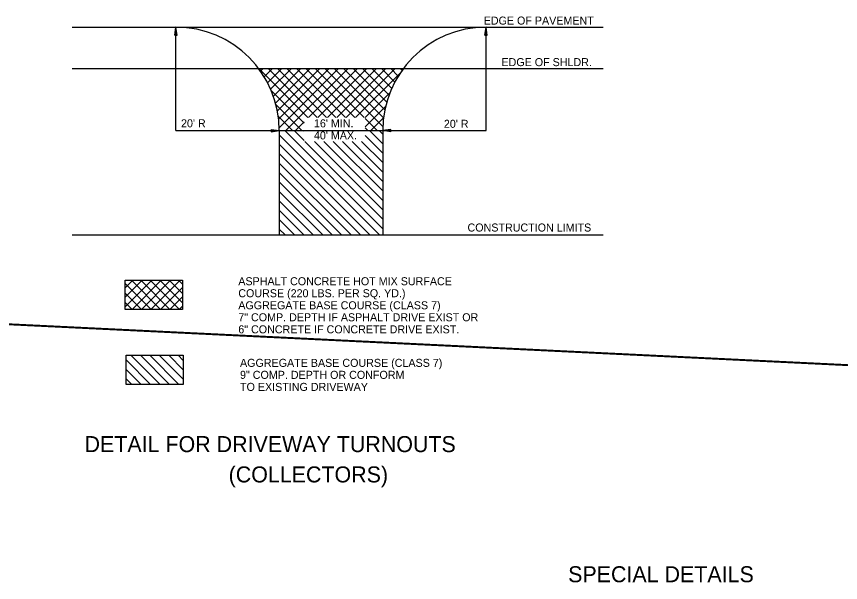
# Model space of a CAD drawing. Extents: x 1227242 to 1227801, y 152460 to 152569.
# Drawn here: x 1227362.27 to 1227375.13, y 152459.8 to 152468.63 of the extents above; entities that cross this region are included whole.
import ezdxf

# ---------------------------------------------------------------- set-up
doc = ezdxf.new("R2010")
doc.units = 0
for name, color, linetype in [('Default', 7, 'Continuous'), ('R_Dimension', 7, 'Continuous'), ('R_Draft', 7, 'Continuous')]:
    doc.layers.add(name, color=color, linetype=linetype)

msp = doc.modelspace()

# ---------------------------------------------------------------- linework, layer by layer
at = {"layer": 'Default'}
for p, q in [((1227364.737, 152468.337), (1227364.756, 152468.462)), ((1227364.737, 152468.337), (1227364.756, 152468.462)), ((1227364.74, 152468.337), (1227364.756, 152468.441)), ((1227364.74, 152468.337), (1227364.756, 152468.441)), ((1227364.756, 152466.847), (1227364.756, 152468.462)), ((1227364.774, 152468.337), (1227364.756, 152468.462)), ((1227364.774, 152468.337), (1227364.756, 152468.462)), ((1227364.771, 152468.337), (1227364.756, 152468.441)), ((1227364.771, 152468.337), (1227364.756, 152468.441)), ((1227369.58, 152468.337), (1227369.598, 152468.462)), ((1227369.58, 152468.337), (1227369.598, 152468.462)), ((1227369.583, 152468.337), (1227369.598, 152468.441)), ((1227369.583, 152468.337), (1227369.598, 152468.441)), ((1227369.598, 152466.847), (1227369.598, 152468.462)), ((1227369.617, 152468.337), (1227369.598, 152468.462)), ((1227369.617, 152468.337), (1227369.598, 152468.462)), ((1227369.614, 152468.337), (1227369.598, 152468.441)), ((1227369.614, 152468.337), (1227369.598, 152468.441)), ((1227364.737, 152468.337), (1227364.774, 152468.337)), ((1227364.737, 152468.337), (1227364.774, 152468.337)), ((1227364.743, 152468.337), (1227364.756, 152468.419)), ((1227364.743, 152468.337), (1227364.756, 152468.419)), ((1227364.746, 152468.337), (1227364.756, 152468.398)), ((1227364.746, 152468.337), (1227364.756, 152468.398)), ((1227364.75, 152468.337), (1227364.756, 152468.377)), ((1227364.75, 152468.337), (1227364.756, 152468.377)), ((1227364.753, 152468.337), (1227364.756, 152468.356)), ((1227364.753, 152468.337), (1227364.756, 152468.356)), ((1227364.768, 152468.337), (1227364.756, 152468.419)), ((1227364.768, 152468.337), (1227364.756, 152468.419)), ((1227364.765, 152468.337), (1227364.756, 152468.398)), ((1227364.765, 152468.337), (1227364.756, 152468.398)), ((1227364.762, 152468.337), (1227364.756, 152468.377)), ((1227364.762, 152468.337), (1227364.756, 152468.377)), ((1227364.759, 152468.337), (1227364.756, 152468.356)), ((1227364.759, 152468.337), (1227364.756, 152468.356)), ((1227369.58, 152468.337), (1227369.617, 152468.337)), ((1227369.58, 152468.337), (1227369.617, 152468.337)), ((1227369.586, 152468.337), (1227369.598, 152468.419)), ((1227369.586, 152468.337), (1227369.598, 152468.419)), ((1227369.589, 152468.337), (1227369.598, 152468.398)), ((1227369.589, 152468.337), (1227369.598, 152468.398)), ((1227369.592, 152468.337), (1227369.598, 152468.377)), ((1227369.592, 152468.337), (1227369.598, 152468.377)), ((1227369.595, 152468.337), (1227369.598, 152468.356)), ((1227369.595, 152468.337), (1227369.598, 152468.356)), ((1227369.611, 152468.337), (1227369.598, 152468.419)), ((1227369.611, 152468.337), (1227369.598, 152468.419)), ((1227369.608, 152468.337), (1227369.598, 152468.398)), ((1227369.608, 152468.337), (1227369.598, 152468.398)), ((1227369.605, 152468.337), (1227369.598, 152468.377)), ((1227369.605, 152468.337), (1227369.598, 152468.377)), ((1227369.601, 152468.337), (1227369.598, 152468.356)), ((1227369.601, 152468.337), (1227369.598, 152468.356)), ((1227366.813, 152467.051), (1227366.048, 152467.816)), ((1227366.076, 152467.775), (1227366.117, 152467.816)), ((1227366.134, 152467.686), (1227366.264, 152467.816)), ((1227366.187, 152467.592), (1227366.412, 152467.816)), ((1227366.96, 152467.051), (1227366.195, 152467.816)), ((1227366.235, 152467.492), (1227366.559, 152467.816)), ((1227366.277, 152467.386), (1227366.706, 152467.816)), ((1227366.312, 152467.274), (1227366.853, 152467.816)), ((1227366.34, 152467.155), (1227367.001, 152467.816)), ((1227367.107, 152467.051), (1227366.343, 152467.816)), ((1227366.359, 152467.027), (1227367.148, 152467.816)), ((1227366.368, 152466.889), (1227367.295, 152467.816)), ((1227366.474, 152466.847), (1227367.443, 152467.816)), ((1227367.255, 152467.051), (1227366.49, 152467.816)), ((1227367.402, 152467.051), (1227366.637, 152467.816)), ((1227367.549, 152467.051), (1227366.784, 152467.816)), ((1227366.825, 152467.051), (1227367.59, 152467.816)), ((1227367.696, 152467.051), (1227366.932, 152467.816)), ((1227366.973, 152467.051), (1227367.737, 152467.816)), ((1227367.986, 152466.909), (1227367.079, 152467.816)), ((1227367.12, 152467.051), (1227367.885, 152467.816)), ((1227367.997, 152467.045), (1227367.226, 152467.816)), ((1227367.267, 152467.051), (1227368.032, 152467.816)), ((1227368.018, 152467.172), (1227367.374, 152467.816)), ((1227367.415, 152467.051), (1227368.179, 152467.816)), ((1227368.047, 152467.29), (1227367.521, 152467.816)), ((1227368.083, 152467.402), (1227367.668, 152467.816)), ((1227368.125, 152467.506), (1227367.816, 152467.816)), ((1227368.174, 152467.605), (1227367.963, 152467.816)), ((1227368.228, 152467.699), (1227368.11, 152467.816)), ((1227368.287, 152467.787), (1227368.258, 152467.816)), ((1227367.562, 152467.051), (1227368.262, 152467.751)), ((1227366.756, 152466.961), (1227366.242, 152467.474)), ((1227367.709, 152467.051), (1227368.097, 152467.439)), ((1227366.722, 152466.847), (1227366.317, 152467.252)), ((1227367.711, 152466.906), (1227368.03, 152467.224)), ((1227366.575, 152466.847), (1227366.355, 152467.067)), ((1227367.9, 152466.847), (1227367.711, 152467.037)), ((1227367.8, 152466.847), (1227367.997, 152467.044)), ((1227366.622, 152466.847), (1227366.756, 152466.982)), ((1227364.756, 152466.847), (1227366.37, 152466.847)), ((1227366.245, 152466.866), (1227366.37, 152466.847)), ((1227366.245, 152466.866), (1227366.245, 152466.829)), ((1227366.245, 152466.866), (1227366.37, 152466.847)), ((1227366.245, 152466.866), (1227366.245, 152466.829)), ((1227366.245, 152466.863), (1227366.349, 152466.847)), ((1227366.245, 152466.863), (1227366.349, 152466.847)), ((1227366.245, 152466.86), (1227366.328, 152466.847)), ((1227366.245, 152466.86), (1227366.328, 152466.847)), ((1227366.245, 152466.857), (1227366.307, 152466.847)), ((1227366.245, 152466.857), (1227366.307, 152466.847)), ((1227366.245, 152466.853), (1227366.286, 152466.847)), ((1227366.245, 152466.853), (1227366.286, 152466.847)), ((1227366.245, 152466.85), (1227366.265, 152466.847)), ((1227366.245, 152466.85), (1227366.265, 152466.847)), ((1227366.245, 152466.829), (1227366.37, 152466.847)), ((1227366.245, 152466.841), (1227366.286, 152466.847)), ((1227366.245, 152466.835), (1227366.328, 152466.847)), ((1227366.245, 152466.832), (1227366.349, 152466.847)), ((1227366.245, 152466.838), (1227366.307, 152466.847)), ((1227366.245, 152466.844), (1227366.265, 152466.847)), ((1227366.245, 152466.829), (1227366.37, 152466.847)), ((1227366.245, 152466.841), (1227366.286, 152466.847)), ((1227366.245, 152466.835), (1227366.328, 152466.847)), ((1227366.245, 152466.832), (1227366.349, 152466.847)), ((1227366.245, 152466.838), (1227366.307, 152466.847)), ((1227366.245, 152466.844), (1227366.265, 152466.847)), ((1227366.37, 152466.847), (1227367.984, 152466.847)), ((1227367.932, 152465.222), (1227366.37, 152466.784)), ((1227367.984, 152465.317), (1227366.454, 152466.847)), ((1227366.756, 152466.693), (1227366.601, 152466.847)), ((1227366.756, 152466.841), (1227366.749, 152466.847)), ((1227367.753, 152466.847), (1227367.711, 152466.89)), ((1227367.984, 152466.496), (1227367.711, 152466.769)), ((1227367.984, 152466.643), (1227367.78, 152466.847)), ((1227367.984, 152466.791), (1227367.927, 152466.847)), ((1227368.109, 152466.866), (1227367.984, 152466.847)), ((1227368.109, 152466.866), (1227367.984, 152466.847)), ((1227367.984, 152466.847), (1227369.598, 152466.847)), ((1227368.109, 152466.829), (1227367.984, 152466.847)), ((1227368.109, 152466.829), (1227367.984, 152466.847)), ((1227368.109, 152466.863), (1227368.005, 152466.847)), ((1227368.109, 152466.863), (1227368.005, 152466.847)), ((1227368.109, 152466.832), (1227368.005, 152466.847)), ((1227368.109, 152466.832), (1227368.005, 152466.847)), ((1227368.109, 152466.86), (1227368.027, 152466.847)), ((1227368.109, 152466.86), (1227368.027, 152466.847)), ((1227368.109, 152466.835), (1227368.027, 152466.847)), ((1227368.109, 152466.835), (1227368.027, 152466.847)), ((1227368.109, 152466.857), (1227368.047, 152466.847)), ((1227368.109, 152466.857), (1227368.047, 152466.847)), ((1227368.109, 152466.838), (1227368.047, 152466.847)), ((1227368.109, 152466.838), (1227368.047, 152466.847)), ((1227368.109, 152466.854), (1227368.069, 152466.847)), ((1227368.109, 152466.854), (1227368.069, 152466.847)), ((1227368.109, 152466.841), (1227368.069, 152466.847)), ((1227368.109, 152466.841), (1227368.069, 152466.847)), ((1227368.109, 152466.85), (1227368.089, 152466.847)), ((1227368.109, 152466.85), (1227368.089, 152466.847)), ((1227368.109, 152466.844), (1227368.089, 152466.847)), ((1227368.109, 152466.844), (1227368.089, 152466.847)), ((1227368.109, 152466.829), (1227368.109, 152466.866)), ((1227368.109, 152466.829), (1227368.109, 152466.866)), ((1227367.785, 152465.222), (1227366.37, 152466.637)), ((1227367.984, 152465.465), (1227366.77, 152466.679)), ((1227367.984, 152465.612), (1227366.917, 152466.679)), ((1227367.984, 152465.759), (1227367.064, 152466.679)), ((1227367.984, 152465.907), (1227367.212, 152466.679)), ((1227367.984, 152466.054), (1227367.359, 152466.679)), ((1227367.984, 152466.201), (1227367.506, 152466.679)), ((1227367.984, 152466.349), (1227367.654, 152466.679)), ((1227367.637, 152465.222), (1227366.37, 152466.49)), ((1227367.49, 152465.222), (1227366.37, 152466.342)), ((1227367.343, 152465.222), (1227366.37, 152466.195)), ((1227367.195, 152465.222), (1227366.37, 152466.048)), ((1227367.048, 152465.222), (1227366.37, 152465.9)), ((1227366.901, 152465.222), (1227366.37, 152465.753)), ((1227366.753, 152465.222), (1227366.37, 152465.606)), ((1227366.606, 152465.222), (1227366.37, 152465.459)), ((1227366.459, 152465.222), (1227366.37, 152465.311)), ((1227363.965, 152464.394), (1227364.083, 152464.513)), ((1227363.965, 152464.247), (1227364.231, 152464.513)), ((1227363.965, 152464.1), (1227364.378, 152464.513)), ((1227364.368, 152464.058), (1227363.965, 152464.462)), ((1227364.515, 152464.058), (1227364.061, 152464.513)), ((1227364.071, 152464.058), (1227364.525, 152464.513)), ((1227364.663, 152464.058), (1227364.208, 152464.513)), ((1227364.218, 152464.058), (1227364.673, 152464.513)), ((1227364.81, 152464.058), (1227364.355, 152464.513)), ((1227364.365, 152464.058), (1227364.82, 152464.513)), ((1227364.857, 152464.159), (1227364.503, 152464.513)), ((1227364.857, 152464.307), (1227364.65, 152464.513)), ((1227364.857, 152464.454), (1227364.797, 152464.513)), ((1227364.513, 152464.058), (1227364.857, 152464.402)), ((1227364.221, 152464.058), (1227363.965, 152464.314)), ((1227364.66, 152464.058), (1227364.857, 152464.255)), ((1227364.073, 152464.058), (1227363.965, 152464.167)), ((1227364.807, 152464.058), (1227364.857, 152464.108)), ((1227364.509, 152462.888), (1227364.054, 152463.343)), ((1227364.656, 152462.888), (1227364.201, 152463.343)), ((1227364.803, 152462.888), (1227364.349, 152463.343)), ((1227364.871, 152462.968), (1227364.496, 152463.343)), ((1227364.871, 152463.115), (1227364.643, 152463.343)), ((1227364.871, 152463.263), (1227364.791, 152463.343)), ((1227364.361, 152462.888), (1227363.979, 152463.271)), ((1227364.214, 152462.888), (1227363.979, 152463.123)), ((1227364.067, 152462.888), (1227363.979, 152462.976))]:
    msp.add_line(p, q, dxfattribs=at)
for points in [[(1227363.965, 152464.513), (1227364.857, 152464.513), (1227364.857, 152464.058), (1227363.965, 152464.058)], [(1227363.979, 152463.343), (1227364.871, 152463.343), (1227364.871, 152462.888), (1227363.979, 152462.888)]]:
    msp.add_lwpolyline(points, close=True, dxfattribs=at)
at = {"layer": 'R_Dimension'}
for points in [[(1227391.101, 152464.336), (1227380.479, 152462.94), (1227348.514, 152464.494)], [(1227394.87, 152464.137), (1227384.248, 152462.741), (1227352.283, 152464.294)]]:
    msp.add_lwpolyline(points, dxfattribs=at)
at = {"layer": 'R_Draft'}
for p, q in [((1227363.139, 152468.462), (1227371.425, 152468.462)), ((1227363.139, 152467.816), (1227371.425, 152467.816)), ((1227366.37, 152466.847), (1227366.37, 152465.222)), ((1227367.984, 152466.847), (1227367.984, 152465.222)), ((1227363.139, 152465.222), (1227371.425, 152465.222))]:
    msp.add_line(p, q, dxfattribs=at)
for centre, start, end in [((1227364.756, 152466.847), 0, 90), ((1227369.598, 152466.847), 90, 180)]:
    msp.add_arc(centre, 1.614, start, end, dxfattribs=at)

# ---------------------------------------------------------------- texts
at = {"layer": 'Default'}
for s, height, p in [('EDGE OF PAVEMENT', 0.125, (1227369.561, 152468.501)), ('EDGE OF SHLDR.', 0.125, (1227369.838, 152467.853)), ("20' R", 0.125, (1227364.836, 152466.899)), ("16' MIN.", 0.125, (1227366.911, 152466.898)), ("20' R", 0.125, (1227368.939, 152466.891)), ("40' MAX.", 0.125, (1227366.911, 152466.71)), ('CONSTRUCTION LIMITS', 0.125, (1227369.308, 152465.273)), ('ASPHALT CONCRETE HOT MIX SURFACE', 0.125, (1227365.73, 152464.435)), ('COURSE (220 LBS. PER SQ. YD.) ', 0.125, (1227365.73, 152464.248)), ('AGGREGATE BASE COURSE (CLASS 7) ', 0.125, (1227365.73, 152464.06)), ('7" COMP. DEPTH IF ASPHALT DRIVE EXIST OR', 0.125, (1227365.73, 152463.873)), ('6" CONCRETE IF CONCRETE DRIVE EXIST.', 0.125, (1227365.73, 152463.685)), ('AGGREGATE BASE COURSE (CLASS 7)', 0.125, (1227365.757, 152463.162)), ('9" COMP. DEPTH OR CONFORM', 0.125, (1227365.757, 152462.975)), ('TO EXISTING DRIVEWAY', 0.125, (1227365.757, 152462.787)), ('DETAIL FOR DRIVEWAY TURNOUTS', 0.25, (1227363.33, 152461.832)), ('(COLLECTORS)', 0.25, (1227365.579, 152461.359))]:
    msp.add_text(s, height=height, dxfattribs=at).set_placement(p)
at = {"layer": 'R_Draft'}
msp.add_text('SPECIAL DETAILS', height=0.25, dxfattribs=at).set_placement((1227370.879, 152459.802))

doc.saveas('drawing.dxf')
